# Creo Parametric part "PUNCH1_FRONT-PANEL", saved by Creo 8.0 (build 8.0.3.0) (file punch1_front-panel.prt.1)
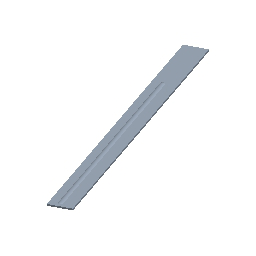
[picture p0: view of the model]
Units: millimeter Newton Second (mmNs); MM, TONNE, SECS

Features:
  1. datum plane "RIGHT"
  2. datum plane "TOP"
  3. datum plane "FRONT"
  4. coordinate system
  5. protrusion
  6. cut
  7. protrusion

Layers: 0_ALL_AXIS, 0_ALL_CSYS, 0_ALL_CURVES, 0_ALL_PLANES, 0_ALL_POINTS, 0_ALL_SURFS, PUNCH1_FRONT-PANEL

Surfaces: 6 plane, 2 torus, 1 cylinder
